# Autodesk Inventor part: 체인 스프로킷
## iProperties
Created: 2014-07
Part Number: 체인 스프로킷
Material: Steel
Document SubType Name: Modeling
Designer: KYOUNG IL JANG
Density: 7.85 g/cm^3
Mass: 738.63 g
Surface Area: 236.842 cm^2
Volume: 94.093 cm^3
CustomPartVersion: 1
Company: 한국ATC센터
Author: KYOUNG IL JANG
